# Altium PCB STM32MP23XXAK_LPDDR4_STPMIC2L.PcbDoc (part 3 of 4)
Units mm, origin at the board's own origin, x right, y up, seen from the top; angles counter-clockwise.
Board outline 120 x 79.6 mm, 4 copper layers (Top Layer, Signal Layer 1, Signal Layer 2, Bottom Layer), stack 1.614 mm thick; 156 components, 124 nets, 1131 pads, 692 vias.
Unrouted connection lines stored in the file: 3.
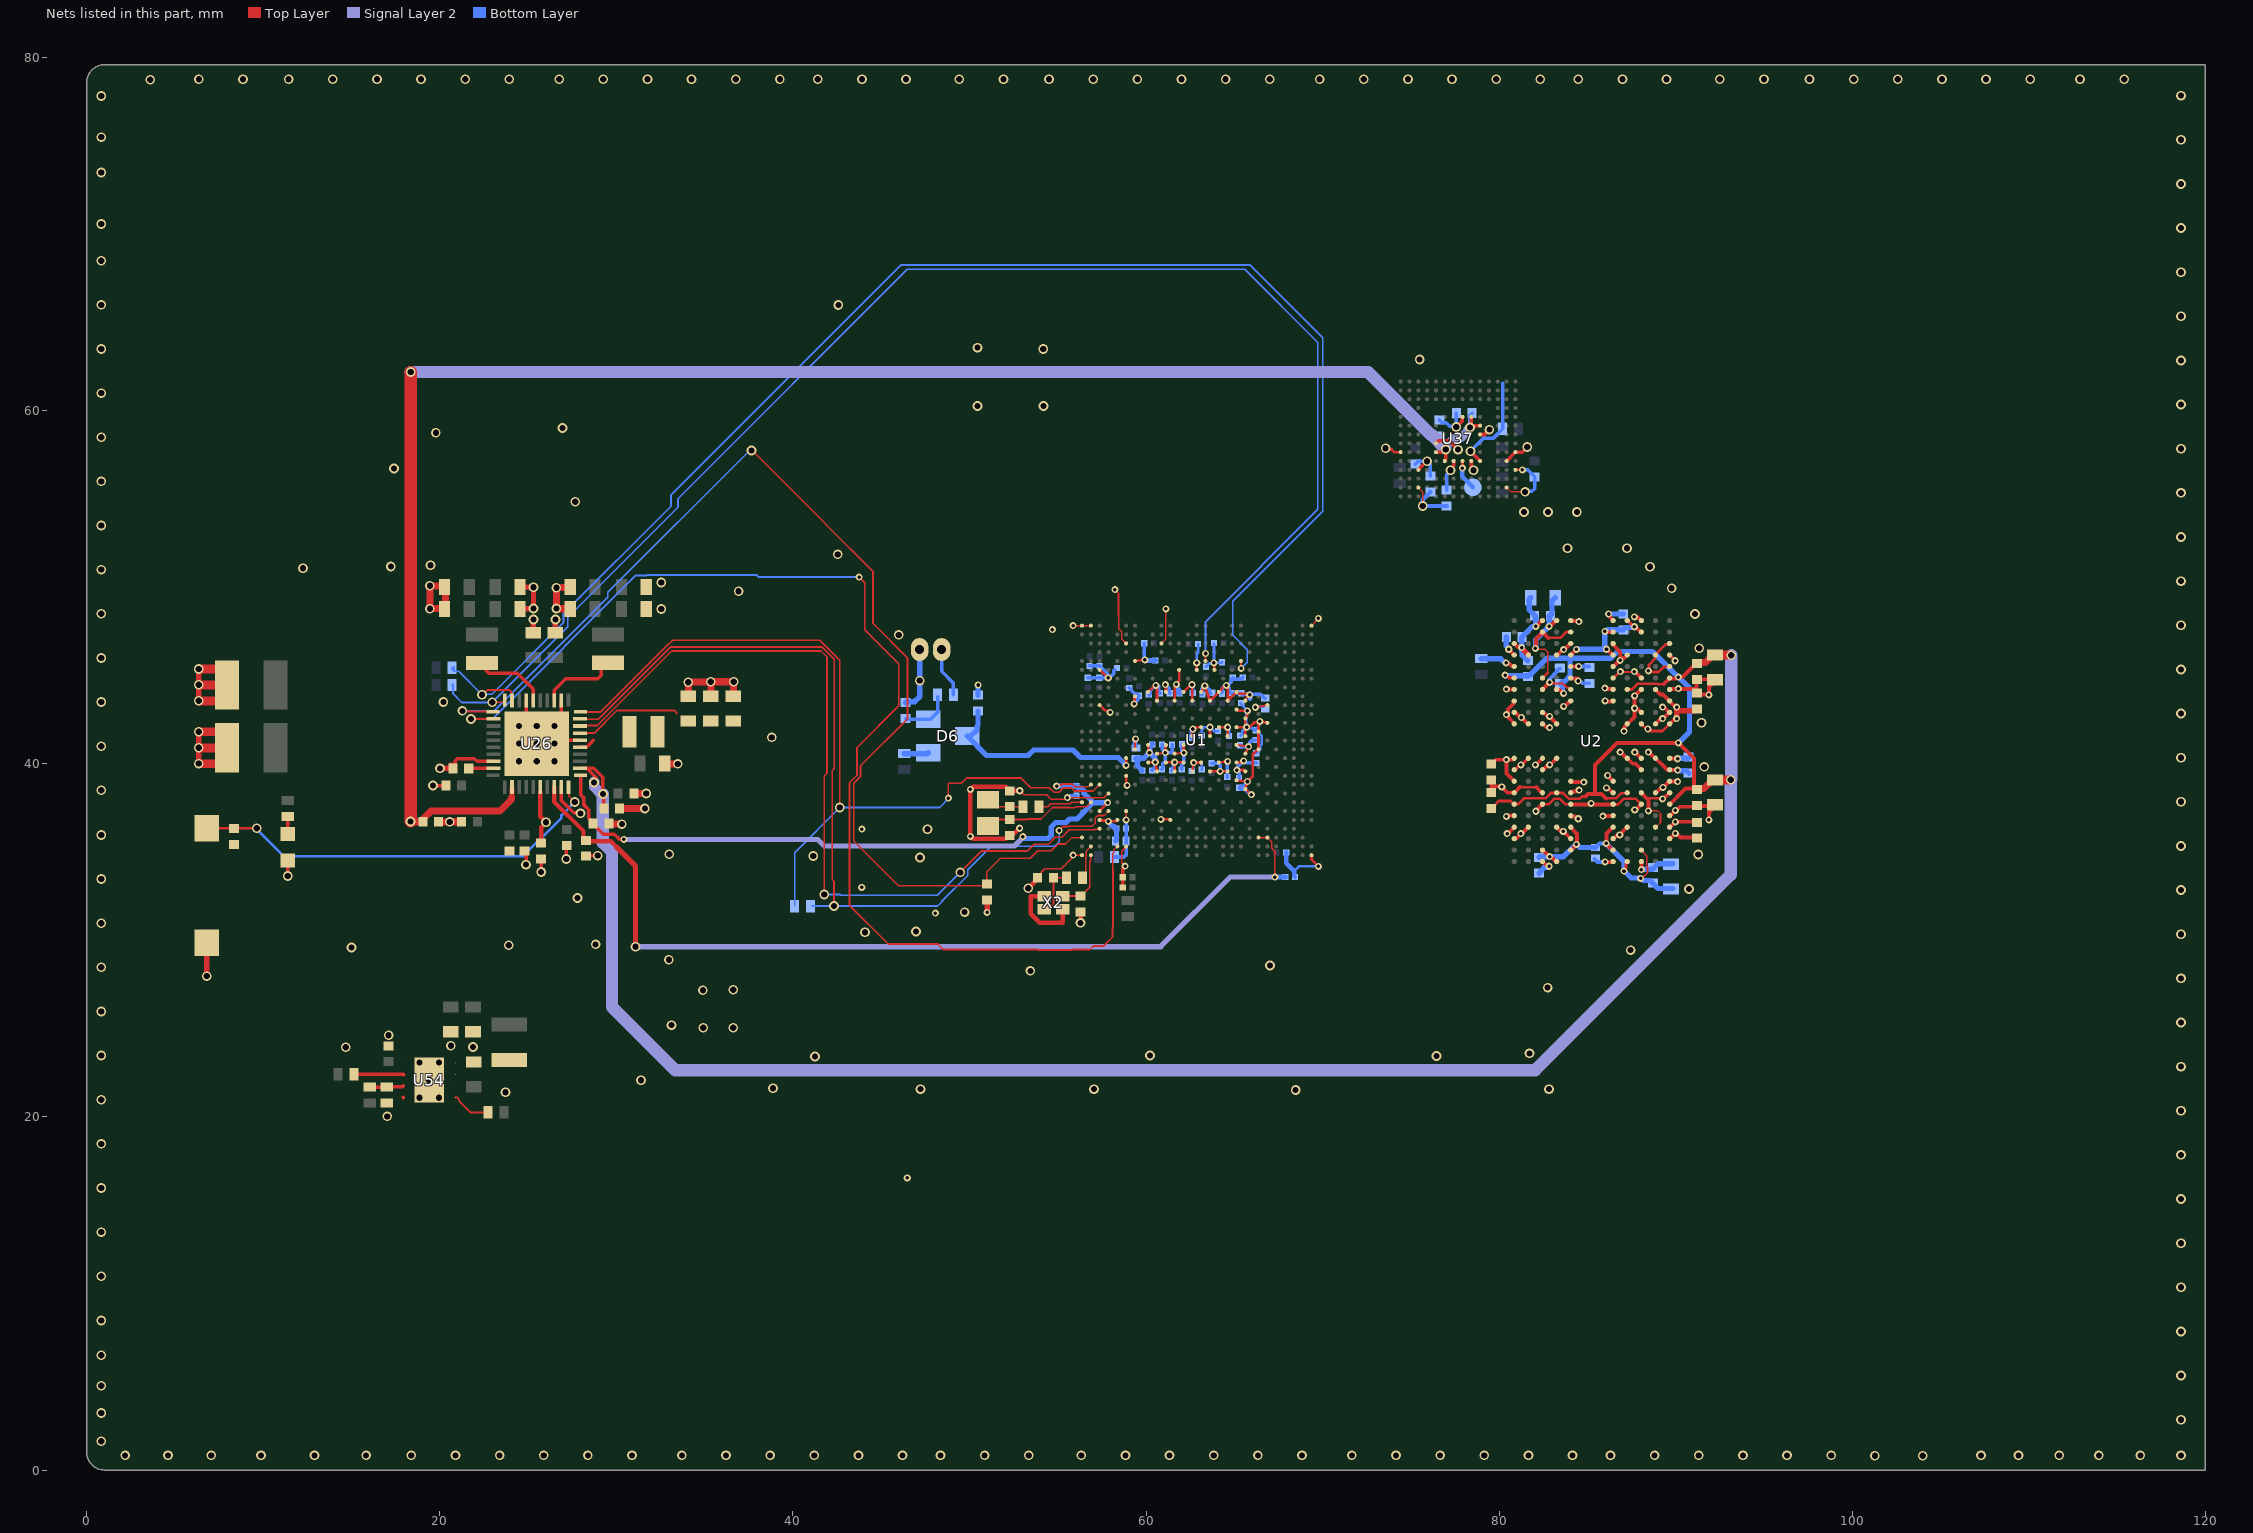
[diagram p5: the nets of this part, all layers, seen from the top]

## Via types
v1: diameter 0.55, hole 0.35, Top Layer to Bottom Layer, 364 vias
v2: diameter 0.4, hole 0.2, Top Layer to Bottom Layer, tented both sides, 223 vias
v3: diameter 0.4, hole 0.2, Top Layer to Bottom Layer, 105 vias

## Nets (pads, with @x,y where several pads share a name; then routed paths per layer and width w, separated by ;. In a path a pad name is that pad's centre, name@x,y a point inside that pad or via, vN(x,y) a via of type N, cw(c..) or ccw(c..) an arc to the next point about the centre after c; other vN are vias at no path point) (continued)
GND: B2.1 C2.1 C3.1 C4.2 C5.2 C6.2 C7.2 C8.2 C9.1 C10.1 C11.1 C12.2 C13.2 C14.2 C15.2 C16.2 C17.2 C18.2 C19.2 C20.2 C21.2 C22.1 C23.1 C24.1 C26.1 C27.1 C28.1 C29.1 C32.1 C33.1 C34.1 C35.1 C36.1 C38.1 C39.1 C40.2 C41.1 C42.2 C44.2 C45.1 C46.1 C47.2 C48.1 C49.1 C50.1 C51.1 C52.1 C53.1 C54.1 C55.1 C56.1 C57.1 C58.1 C59.1 C60.1 C61.2 C62.2 C63.1 C64.1 C65.2 C66.1 C67.1 C68.1 C69.1 C70.2 C71.1 C72.1 C73.2 C74.1 C75.1 C76.1 C77.2 C81.2 C82.1 C83.1 C86.2 C87.1 C88.1 C90.1 C92.2 C117.1 C118.1 C123.1 C128.1 C130.1 C147.2 C148.1 C183.1 C185.2 C189.2 C190.2 C192.1 C193.2 C195.1 C196.1 C197.1 C200.1 C201.1 C202.1 C205.1 C208.1 C209.1 C213.1 C214.1 C215.1 C219.1 C220.1 C225.1 C234.1 C235.1 C236.1 C237.1 C238.1 C239.1 C240.1 C244.1 C246.1 C248.1 C250.1 C251.1 CN12.2 LD11.2 R1.1 R42.1 R57.1 U1.1A1 U1.1A3 U1.1A5 U1.1A7 U1.1A9 U1.1A11 U1.1B2 U1.1B4 U1.1B6 U1.1B8 U1.1B10 U1.1B12 U1.1E7 U1.1E9 U1.1F6 U1.1F8 U1.1F10 U1.1G1 U1.1G3 U1.1G5 U1.1G11 U1.1H2 U1.1H4 U1.1H12 U1.1J1 U1.1J3 U1.1J5 U1.1J7 U1.1J9 U1.1J11 U1.1K2 U1.1K4 U1.1K6 U1.1K8 U1.1K10 U1.1K12 U1.A1 U1.A2 U1.A27 U1.AC3 U1.AC5 U1.AC11 U1.AF6 U1.AG1 U1.AG27 U1.C6 U1.C10 U1.E7 U1.F3 U1.F12 U1.F14 U1.F16 U1.J7 U1.K3 U1.V6 U1.Y4 U2.A3 U2.A10 U2.AB3 U2.AB5 U2.AB8 U2.AB10 U2.C1 U2.C5 U2.C8 U2.C12 U2.D2 U2.D4 U2.D9 U2.D11 U2.E1 U2.E5 U2.E8 U2.E12 U2.G1 U2.G3 U2.G5 U2.G8 U2.G10 U2.G12 U2.J1 U2.J3 U2.J10 U2.J12 U2.K2 U2.K4 U2.K9 U2.K11 U2.N2 U2.N4 U2.N9 U2.N11 U2.P1 U2.P3 U2.P10 U2.P12 U2.T1 U2.T3 U2.T5 U2.T8 U2.T10 U2.T12 U2.V1 U2.V5 U2.V8 U2.V12 U2.W2 U2.W4 U2.W9 U2.W11 U2.Y1 U2.Y5 U2.Y8 U2.Y12 U26.6 U26.12 U26.17 U26.28 U26.39 U26.41 U37.A6 U37.C4 U37.E7 U37.G5 U37.H10 U37.J5 U37.K8 U37.N2 U37.N5 U37.P4 U37.P6 U54.4 U54.8 U54.9 X2.2 X2.4 | length 243
  Top Layer w0.09: v2(55.55,38.085) 55.565,38.07 56.266,38.07 56.271,38.075 57.612,38.075 57.862,38.325 U1.Y4@57.875,38.325 ; U1.A1@56.375,47.825 U1.A2@56.875,47.825 ; 58.445,48.418 58.445,47.647 58.625,47.467 58.625,47.075 U1.C6@58.875,46.825 ; v2(58.816,34.213) 58.625,34.404 58.625,35.05 58.875,35.3 U1.AF6@58.875,35.325 ; U1.C10@60.875,46.825 61.125,47.075 v2(61.125,48.775) ; U37.N2@80.425,55.655 80.675,55.405 v1(81.475,55.405) ; U2.T10@82.459,44.194 U2.T10@82.459,44.207 ; v3@82.859,44.607 82.859,44.619 v3@82.937,44.619 ; v3@86.859,40.669 86.872,40.669 v3@86.884,40.669 ; U2.K4@87.234,40.319 U2.K4@87.259,40.319 ; v3@88.459,37.344 88.467,37.352 88.976,37.352 89.145,37.183 89.145,36.68 U2.D2@88.859,36.394
  Top Layer w0.1: v2(52.85,38.475) 52.882,38.475 53.114,38.244 54.372,38.244 54.622,37.994 55.458,37.994 v2(55.55,38.085) ; v1@53.243,33.041 v1(53.329,32.955) ; C92.2@53.859,33.546 53.859,33.648 54.264,34.053 55.189,34.053 55.279,34.144 55.291,34.144 55.496,34.349 55.496,34.361 55.77,34.635 55.77,34.639 55.875,34.744 v2(55.875,34.825) U1.AG1@56.375,34.825 ; v2(55.875,47.825) U1.A1@56.375,47.825 ; v2(58.24,49.865) 58.445,49.66 58.445,48.418 ; U1.A27@69.375,47.825 69.762,48.213 v2(69.762,48.238) ; v3(83.66,46.465) 83.685,46.465 v3@83.723,46.503 ; U2.Y8@84.035,46.815 U2.Y8@84.06,46.815 ; U2.V8@84.06,45.515 84.064,45.519 U2.V8@84.084,45.519 ; v3@84.505,45.519 v3(84.509,45.523)
  Top Layer w0.125: v3@82.974,44.57 83.12,44.57 83.144,44.545 83.616,44.545 83.835,44.326 83.9,44.326 84.018,44.208 U2.T8@84.018,44.194
  Top Layer w0.15: U1.AC3@57.375,36.825 57.41,36.79 57.795,36.79 57.845,36.74 v2(57.872,36.74) 58.29,36.74 U1.AC5@58.375,36.825 ; U1.K3@57.375,43.325 57.643,43.057 v2(57.966,42.92) ; U1.F3@57.375,45.325 v2(57.862,44.875) ; U1.V6@58.875,39.325 58.875,38.893 58.925,38.843 v2(58.925,38.775) ; v2@59.325,43.275 59.35,43.3 59.35,43.613 ; v2(59.325,43.4) 59.35,43.613 ; U1.E7@59.375,45.825 v2(59.931,45.892) ; U1.J7@59.388,43.812 U1.J7@59.375,43.825 ; U1.1J1@60.125,40.075 v2(60.525,40.1) U1.1K2@60.625,39.575 ; U1.1G1@60.125,41.075 60.125,40.778 60.198,40.705 v2(60.198,40.638) ; U1.1A1@60.125,44.075 60.442,44.392 60.481,44.392 60.531,44.442 v2@60.555,44.442 ; v2(60.558,44.442) v2@60.555,44.442 ; U1.1H2@60.625,40.575 v2(61.092,40.638) U1.1G3@61.125,41.075 ; U1.1B2@60.625,43.575 60.625,44.371 v2@60.555,44.442 ; v2(60.841,36.854) 61.289,36.854 61.303,36.84 61.36,36.84 U1.AC11@61.375,36.825 ; U1.1J3@61.125,40.075 v2(61.625,40.089) ; U1.1A3@61.125,44.075 61.132,44.082 v2@61.132,44.466 ; U1.1K4@61.625,39.575 v2(61.625,40.089) ; U1.1H4@61.625,40.575 v2(62.15,40.625) U1.1G5@62.125,41.075 ; U1.1B4@61.625,43.575 61.625,44.405 v2(61.725,44.505) 61.725,44.573 61.875,44.723 U1.F12@61.875,45.325 ; U1.1J5@62.125,40.075 v2(61.625,40.089) ; U1.1A5@62.125,44.075 62.496,44.446 62.571,44.446 62.625,44.5 U1.1B6@62.625,43.575 ; U1.1K6@62.625,39.575 v2(62.7,40.075) U1.1J7@63.125,40.075 ; U1.1F6@62.625,41.575 62.625,41.95 v2(62.65,41.975) ; v2@62.657,41.975 62.718,41.975 62.818,42.075 U1.1E7@63.125,42.075 ; U1.F14@62.875,45.325 v2(62.875,45.725) ; U1.1A7@63.125,44.075 v2(63.328,44.412) U1.1B8@63.625,43.575 U1.1A9@64.125,44.075 64.448,44.398 64.538,44.398 64.586,44.446 64.625,44.407 U1.1B10@64.625,43.575 U1.1A11@65.125,44.075 65.147,44.075 65.25,43.972 65.818,43.972 65.865,43.925 65.865,43.894 65.64,43.669 65.64,43.59 U1.1B12@65.625,43.575 ; U1.1K8@63.625,39.575 v2(64.198,39.575) U1.1K10@64.625,39.575 ; U1.1F8@63.625,41.575 v2(63.625,42.075) ; v2@63.853,45.725 U1.F16@63.875,45.325 ; U1.1E9@64.125,42.075 v2(64.625,42.075) U1.1F10@64.625,41.575 ; U1.1G11@65.125,41.075 v2(65.806,40.972) U1.1H12@65.625,40.575 ; U1.AG27@69.375,34.825 69.375,34.59 v2(69.768,34.197) ; v1(73.575,57.875) 73.646,57.804 73.911,57.804 74.056,57.66 74.42,57.66 U37.A6@74.425,57.655 ; U37.P4@80.925,56.655 v2(81.325,56.655) ; 81.193,38.681 81.527,38.681 81.531,38.684 81.791,38.684 81.795,38.681 82.106,38.681 ; v3@82.937,44.619 82.937,44.609 82.974,44.572 v3@82.974,44.57 ; U2.T8@84.018,44.194 U2.T8@84.059,44.194 ; 88.348,38.055 88.724,38.055 88.729,38.05 89.228,38.05 v3@89.259,38.019 ; U2.W2@88.859,46.169 88.859,46.196 89.433,46.77 89.562,46.77 U2.Y1@89.608,46.816 ; U2.W2@88.86,46.168 88.843,46.151 88.843,45.957 88.495,45.609 88.495,45.298 88.45,45.253 88.486,45.217 88.711,45.217 88.729,45.2 89.033,45.2 89.334,45.501 U2.V1@89.652,45.501 ; 59.35,43.613 59.35,43.825 U1.J7@59.375,43.825 ; 59.35,43.613 U1.J7@59.375,43.825
  Top Layer w0.16: U1.1J9@64.125,40.075 v2(64.625,40.143) ; U1.1J11@65.125,40.075 65.435,40.075 v2(65.53,40.17) ; v2(65.15,39.65) 65.55,39.65 U1.1K12@65.625,39.575
  Top Layer w0.2: v1@11.386,33.645 LD11.2@11.386,34.522 ; U54.4@17.926,21.107 17.936,21.097 ; v1(19.613,38.769) C209.1@20.288,38.769 ; C208.1@20.582,39.981 C208.1@20.719,39.981 ; C208.1@20.719,39.819 C208.1@20.719,39.981 ; U26.28@23.038,40.144 22.112,40.144 21.957,40.299 20.991,40.299 20.874,40.182 20.874,39.999 20.857,39.981 C208.1@20.719,39.981 ; v1@24.888,34.292 C123.1@24.888,35.119 ; U26.17@24.888,43.594 24.888,41.744 v1(25.488,41.144) U26.41@25.668,41.324 ; v1(25.738,33.869) C215.1@25.738,34.519 ; U26.41@26.386,41.185 26.544,41.344 U26.6@27.938,41.344 ; U26.41@26.386,41.324 U26.41@25.668,41.324 ; U26.39@26.888,38.694 26.888,37.919 27.58,37.226 27.932,37.226 v1(27.963,37.196) ; U26.12@26.888,43.594 26.888,42.544 U26.41@25.668,41.324 ; v1@27.163,34.587 C193.2@27.163,35.389 ; C61.2@28.307,34.8 28.322,34.784 28.934,34.784 v1(28.95,34.8) ; C248.1@58.683,33.002 C250.1@58.683,33.572 58.683,34.08 v2(58.816,34.213) ; U37.C4@75.425,56.655 75.875,57.105 75.885,57.105 v1(75.925,57.145) ; U37.E7@76.425,58.155 76.575,58.305 77.17,58.305 v1(77.675,57.8) ; v1(77.25,56.63) 77.25,56.718 77.425,56.893 U37.G5@77.425,57.155 ; v1(77.575,59.08) 77.925,59.43 U37.H10@77.925,59.655 ; U37.J5@78.425,57.155 78.425,56.85 78.55,56.725 v1(78.55,56.63) ; U37.K8@78.925,58.655 79.175,58.655 v1(79.45,58.93) ; U37.N5@80.425,57.155 U37.P6@80.925,57.655 81.305,57.655 v1(81.6,57.95) ; U2.J12@80.86,39.665 80.914,39.665 81.164,39.915 81.247,39.915 81.648,40.315 U2.K11@81.66,40.315
  Top Layer w0.22: C5.2@79.559,38.379 79.559,38.73 ; C13.2@79.559,39.08 79.559,38.73 ; v3@80.151,38.625 v3@80.2,38.625 ; v3(80.4,45.719) 80.527,45.719 80.693,45.554 80.765,45.554 80.788,45.53 80.85,45.53 U2.V12@80.86,45.521 ; v3@80.41,37.025 80.45,37.065 U2.E12@80.86,37.065 ; v3@80.425,44.215 U2.T12@80.86,44.215 ; U2.G12@80.83,38.38 U2.G12@80.845,38.365 ; U2.G12@80.854,38.356 U2.G12@80.845,38.365 ; U2.P12@80.859,42.894 80.874,42.879 80.949,42.879 81.149,42.679 81.17,42.679 81.293,42.556 81.293,42.535 81.347,42.535 81.637,42.244 U2.N11@81.659,42.244 ; U2.C12@80.86,35.765 80.875,35.78 80.975,35.78 v3(81.24,36.045) 81.288,36.045 U2.D11@81.658,36.415 ; U2.G12@80.86,38.365 U2.G12@80.845,38.365 ; U2.Y12@80.86,46.815 80.882,46.815 81.073,46.623 81.236,46.623 v3(81.271,46.589) ; U2.G12@80.87,38.36 81.19,38.681 81.193,38.681 ; v3(82.085,47.79) 82.113,47.79 82.438,48.115 U2.AB10@82.46,48.115 ; 82.106,38.681 82.378,38.409 82.399,38.409 82.452,38.356 U2.G10@82.456,38.356 ; U2.A10@82.459,34.444 82.465,34.45 82.496,34.45 82.716,34.229 82.799,34.229 v3@82.833,34.195 ; U2.J10@82.459,39.644 82.481,39.644 82.721,39.885 82.825,39.885 82.859,39.919 82.872,39.919 83.247,40.294 U2.K9@83.259,40.294 ; U2.P10@82.459,42.894 82.474,42.879 82.557,42.879 82.842,42.594 v3@82.897,42.594 ; U2.T10@82.459,44.207 v3@82.859,44.607 ; v3(82.86,42.69) 82.859,42.677 83.259,42.278 U2.N9@83.259,42.265 ; U2.W9@83.259,46.144 83.281,46.144 83.571,46.435 83.625,46.435 83.693,46.503 v3@83.723,46.503 ; U2.D9@83.26,36.415 83.5,36.175 v3(83.635,36.175) ; v3@83.641,36.175 U2.C8@84.059,35.756 ; v3@83.747,46.503 v3@83.723,46.503 ; U2.Y8@84.035,46.815 v3@83.723,46.503 ; U2.E8@84.059,37.044 84.074,37.029 84.301,37.029 84.435,36.894 v3@84.484,36.894 ; U2.G8@84.059,38.365 84.081,38.365 84.16,38.444 84.336,38.444 84.372,38.481 84.497,38.481 v3@84.534,38.444 ; U2.AB8@84.06,48.115 84.075,48.1 84.421,48.1 84.466,48.054 v3(84.515,48.054) ; U2.V8@84.072,45.507 U2.V8@84.084,45.519 ; U2.V8@84.088,45.523 U2.V8@84.084,45.519 ; v3@84.505,45.519 U2.V8@84.084,45.519 ; v3@85.885,37.04 85.891,37.046 86.384,37.046 86.388,37.05 86.445,37.05 U2.E5@86.46,37.065 ; v3(85.99,44.285) 86.039,44.285 86.093,44.23 86.445,44.23 U2.T5@86.46,44.215 ; v3(86.085,38.64) 86.118,38.606 86.197,38.606 U2.G5@86.446,38.356 ; v3(86.21,48.489) 86.244,48.455 86.244,48.352 86.46,48.137 U2.AB5@86.46,48.115 ; U2.C5@86.459,35.744 86.461,35.744 86.663,35.946 86.791,35.946 U2.D4@87.26,36.415 ; U2.V5@86.46,45.515 86.482,45.515 86.832,45.865 v3(86.86,45.865) v3@86.86,45.988 ; U2.Y5@86.46,46.815 86.475,46.8 86.475,46.716 86.86,46.331 v3@86.86,45.988 ; v3@86.8,35.946 v3(86.835,35.981) ; v3@86.872,40.669 87.247,40.294 U2.K4@87.259,40.294 ; v3(87.075,41.85) 87.109,41.884 87.109,42.093 U2.N4@87.26,42.243 ; U2.K4@87.259,40.315 87.57,40.004 87.72,40.004 U2.J3@88.059,39.665 ; U2.N4@87.26,42.265 U2.N4@87.26,42.243 ; U2.W4@87.26,46.165 87.083,45.988 v3@86.86,45.988 ; v3(87.661,48.325) 87.695,48.291 87.863,48.291 88.038,48.115 U2.AB3@88.06,48.115 ; v3@87.678,43.153 87.715,43.116 87.838,43.116 88.038,42.915 U2.P3@88.06,42.915 ; v3@88.059,33.994 U2.A3@88.059,34.444 ; U2.G3@88.059,38.344 88.348,38.055 88.459,37.944 v3@88.459,37.344 ; U2.T3@88.06,44.215 88.04,44.215 v3(87.675,43.85) v3(87.675,43.15) 87.675,42.658 U2.N4@87.26,42.243 ; v3@88.459,40.669 88.472,40.669 88.847,40.294 U2.K2@88.859,40.294 ; U2.N2@88.859,42.244 89.15,42.535 89.225,42.535 v3@89.259,42.569 ; U2.K2@88.86,40.315 89.531,39.644 89.659,39.644 v3@90.109,39.644 ; v3@89.259,38.019 89.293,38.053 89.347,38.053 89.637,38.344 U2.G1@89.659,38.344 ; v3@89.259,43.219 89.334,43.219 U2.P1@89.638,42.915 ; v3(89.26,42.565) 89.288,42.565 U2.P1@89.638,42.915 ; U2.C1@89.659,35.744 89.954,36.039 v3@89.954,36.147 ; U2.E1@89.659,37.044 89.672,37.044 89.972,37.344 90.033,37.344 90.258,37.569 C7.2@91.159,37.569 ; U2.P1@89.659,42.894 U2.P1@89.638,42.915 ; U2.T1@89.659,44.194 U2.T1@89.681,44.194 ; U2.T1@89.659,44.244 C14.2@91.184,44.244 ; U2.P1@89.66,42.915 U2.P1@89.638,42.915 ; v3@90.033,36.069 90.033,36.066 90.068,36.031 90.071,36.031 90.283,35.819 C15.2@91.159,35.819 ; C7.2@91.159,37.694 C7.2@91.247,37.607 ; C7.2@91.245,37.606 92.095,37.606 C3.1@92.183,37.519 ; C14.2@91.263,43.939 91.85,43.939 v3(91.884,43.905) 91.899,43.92 91.899,44.36 92.083,44.544 91.833,44.794 91.184,44.794 C14.2@91.184,44.244 ; C14.2@91.264,43.939 91.184,44.019 C14.2@91.184,44.244 ; v3(91.884,36.829) 91.899,36.845 91.899,37.255 92.138,37.494 92.233,37.494 C3.1@92.208,37.519 ; 79.559,38.73 80.121,38.73 v3(80.15,38.7) 80.485,38.365 U2.G12@80.845,38.365
  Top Layer w0.25: v2(52.841,36.352) 52.569,36.08 52.415,36.08 C86.2@52.285,35.95 52.26,35.95 52.061,35.75 50.196,35.75 v2(50.05,35.897) v2(50.05,38.554) 50.196,38.7 52.06,38.7 C81.2@52.285,38.475 v2(52.85,38.475) ; v1(53.329,32.955) 53.729,33.355 53.729,33.416 C92.2@53.859,33.546 ; X2.2@54.234,32.51 53.467,32.51 53.467,31.513 53.987,30.993 55.284,30.993 X2.4@55.284,31.76 ; v1(56.293,30.993) C90.1@56.293,31.61
  Top Layer w0.3: v1@6.347,40.012 v1@6.347,41.812 ; v1@6.347,43.574 v1@6.347,45.374 ; B2.1@6.795,29.854 6.795,27.98 v1(6.8,27.975) ; v1(20.013,39.744) C208.1@20.738,39.744 ; U26.41@24.468,40.124 v1(24.488,40.144) v1(25.488,41.144) ; C23.1@24.509,49.935 24.584,50.009 25.291,50.009 25.308,49.992 25.308,48.808 25.284,48.784 24.607,48.784 C24.1@24.558,48.834 ; v1(25.3,48.175) 25.294,48.169 25.294,47.454 C29.1@25.336,47.412 ; C38.1@26.538,47.414 26.544,47.42 26.544,48.169 v1(26.55,48.175) ; v2@50.979,31.565 v2(51,31.586) C33.1@51,32.3 ; v3(80.41,44.23) v3@80.425,44.215 ; v3(81.271,46.589) 81.271,46.562 81.66,46.173 U2.W11@81.66,46.165
  Top Layer w0.4: v1(19.436,48.785) v1(19.436,50.085) C22.1@20.143,50.085 ; v1@19.535,48.789 C183.1@20.238,48.789 ; C190.2@19.888,36.764 19.938,36.714 v1(20.563,36.714) ; C22.1@20.143,49.835 20.263,49.955 C22.1@20.263,50.019 ; C183.1@20.316,48.994 C22.1@20.316,50.064 ; v1@20.568,36.719 C185.2@21.238,36.719 ; C27.1@27.384,50.009 27.372,49.997 26.622,49.997 v1(26.6,49.975) v1(26.6,48.8) 26.616,48.784 C26.1@27.409,48.784 ; C189.2@29.613,36.589 v1@30.307,36.589 ; C40.2@30.143,37.469 C40.2@30.188,37.469 v1(31.613,37.469) ; C39.1@31,38.325 31.006,38.319 v1(31.688,38.319) ; C32.1@32.7,40 v1(33.475,40) ; C200.1@34.075,43.895 v1(34.075,44.625) 34.087,44.638 35.338,44.638 v1(35.35,44.65) ; C202.1@35.453,43.829 35.35,43.932 v1(35.35,44.65) ; C41.1@36.625,43.825 36.638,43.838 36.638,44.638 v1@36.64,44.64 ; v1(36.65,44.65) v1(35.35,44.65)
  Top Layer w0.5: v1@6.353,40.006 C147.2@7.936,40.006 ; v1@6.353,40.906 C147.2@7.936,40.906 ; v1@6.353,41.818 C147.2@7.936,41.818 ; v1@6.353,43.568 C42.2@7.936,43.568 ; v1@6.353,44.468 C42.2@7.936,44.468 ; v1@6.353,45.38 C42.2@7.936,45.38
  Bottom Layer w0.1: C8.2@83.459,45.39 83.459,45.438 C8.2@83.461,45.44
  Bottom Layer w0.15: v2(59.931,45.892) v2@59.935,45.896 ; C57.1@62.592,39.603 62.683,39.694 62.683,40.058 v2(62.7,40.075) 63.066,40.075 63.154,39.987 C60.1@63.154,39.672 ; v2(62.875,45.725) 62.875,46.219 62.95,46.294 C195.1@62.95,46.787 ; C52.1@63.162,41.607 63.162,41.944 63.293,42.075 v2(63.625,42.075) 63.844,41.856 C53.1@64.083,41.856 ; C67.1@63.4,45.5 63.586,45.686 63.807,45.686 v2@63.859,45.738 ; v2(63.85,45.725) 64.278,45.725 C69.1@64.305,45.752 ; v2@63.85,45.775 C239.1@63.85,46.787 ; v2(64.625,42.075) 64.706,41.994 C54.1@64.706,41.579 ; 68.39,33.919 68.669,34.197 v2(69.768,34.197)
  Bottom Layer w0.2: v2(55.55,38.085) 55.663,38.198 C234.1@56.064,38.198 ; C237.1@56.696,44.88 C236.1@57.345,44.88 ; C192.1@56.8,45.55 C201.1@57.375,45.55 57.825,45.1 57.825,44.912 v2(57.862,44.875) 57.862,44.894 57.881,44.914 57.974,44.914 58.163,45.103 58.163,45.282 C197.1@58.216,45.334 ; C236.1@57.35,44.875 v2(57.862,44.875) ; C240.1@59.05,44.3 59.37,43.98 59.484,43.98 59.534,43.93 C220.1@59.534,43.856 ; v2(59.325,43.4) 59.325,43.408 59.534,43.617 59.534,43.781 C220.1@59.609,43.856 C220.1@59.534,43.931 ; v2@59.902,45.948 C205.1@59.902,46.829 ; C45.1@60.173,43.895 60.235,43.957 60.235,44.124 60.248,44.137 60.248,44.139 60.551,44.442 v2(60.558,44.442) ; C71.1@60.34,39.635 60.491,39.786 60.491,40.066 v2(60.525,40.1) ; v2@60.624,44.485 60.726,44.383 60.726,44.075 C51.1@60.813,43.988 ; C72.1@60.905,39.698 60.956,39.749 60.956,40.021 61.092,40.157 v2(61.092,40.638) ; C46.1@60.915,41.105 60.915,40.815 v2(61.092,40.638) ; v2@61.132,44.466 61.132,44.444 61.302,44.274 61.302,44.062 C49.1@61.377,43.987 ; C73.2@61.467,39.624 61.542,39.699 61.542,39.952 61.625,40.035 v2(61.625,40.089) ; C47.2@61.476,41.081 61.476,40.694 61.42,40.638 v2(61.092,40.638) ; C74.1@62.03,39.683 62.03,39.955 62.15,40.075 v2(62.15,40.625) 62.038,40.737 C48.1@62.038,41.107 ; C63.1@62.581,44.08 62.636,44.08 62.636,44.483 v2@62.625,44.494 ; C62.2@63.156,43.924 63.156,44.24 v2(63.328,44.412) 63.366,44.374 63.421,44.374 63.6,44.195 63.6,44.059 C65.2@63.675,43.984 ; C59.1@63.714,40.036 64.111,40.036 64.198,39.949 v2(64.198,39.575) ; C68.1@64.239,43.997 64.314,44.072 64.314,44.284 64.437,44.408 64.548,44.408 v2@64.586,44.446 ; C58.1@64.607,39.247 64.607,40.125 v2(64.625,40.143) ; C66.1@64.915,44.871 C66.1@64.84,44.796 ; C76.1@65.274,39.198 65.274,39.526 v2(65.15,39.65) 65.169,39.669 65.169,39.809 v2(65.53,40.17) 65.557,40.17 65.677,40.05 C77.2@66.25,40.05 ; C82.1@65.352,41.053 65.433,40.972 v2(65.806,40.972) 65.844,41.01 65.844,41.178 66.016,41.35 C75.1@66.205,41.35 ; C238.1@65.483,44.894 65.385,44.796 C66.1@64.84,44.796 ; R1.1@66.751,43.72 66.701,43.72 66.601,43.82 66.601,43.828 66.484,43.946 65.886,43.946 65.865,43.925 65.851,43.939 65.436,43.939 65.375,44 C64.1@64.85,44 64.804,44 64.8,43.996 64.725,44.071 64.725,44.307 v2@64.586,44.446 ; C118.1@75.26,56.98 75.425,57.145 v1(75.925,57.145) 76.11,56.96 C148.1@76.11,56.305 ; C9.1@76.615,59.48 76.77,59.325 77.008,59.325 77.208,59.126 77.529,59.126 v1(77.575,59.08) C117.1@77.575,59.864 ; C130.1@77.027,55.505 77.027,56.407 v1(77.25,56.63) ; v2(81.325,56.655) 81.615,56.655 C128.1@82.015,56.255 82.015,55.592 81.858,55.435 81.505,55.435 v1(81.475,55.405) ; v2@64.586,44.446 64.623,44.446 64.84,44.663 C66.1@64.84,44.796
  Bottom Layer w0.22: v3@82.825,44.749 82.814,44.76 83.291,45.236 83.291,45.295 83.386,45.39 C8.2@83.459,45.39 ; v3(82.86,44.615) 82.893,44.649 v3@82.893,44.777 ; v3(84.509,45.523) 84.511,45.525 C21.2@85.109,45.525
  Bottom Layer w0.25: 67.941,34.367 68.39,33.919 68.39,33.638 C251.1@68.44,33.588 ; 67.941,34.385 C246.1@67.941,34.986
  Bottom Layer w0.3: C88.1@46.382,43.465 46.439,43.522 46.897,43.522 47.189,43.814 CN12.2@47.189,46.897 ; C87.1@50.485,43.888 v2(50.485,44.466) ; v2(57.872,36.74) 57.891,36.721 57.891,36.682 58.133,36.44 58.216,36.44 C244.1@58.325,36.331 58.325,35.675 C235.1@58.275,35.625 ; C70.2@59.775,39.625 59.506,39.894 59.506,40.25 59.456,40.3 C225.1@59.425,40.3 59.451,40.326 59.886,40.326 v2(60.198,40.638) ; v2@59.902,45.948 59.931,45.919 v2(59.931,45.892) 59.958,45.892 60,45.85 C196.1@60.525,45.85 ; C44.2@60.351,41.105 60.217,40.971 60.217,40.657 v2(60.198,40.638) ; v2(60.525,40.1) 60.506,40.119 60.506,40.33 v2(60.198,40.638) ; v2(61.725,44.505) 61.725,44.478 61.75,44.453 61.75,44.284 61.875,44.159 61.875,44.025 C50.1@61.9,44 ; C55.1@62.6,41.475 62.604,41.479 62.604,41.901 62.65,41.948 v2(62.65,41.975) ; v2@65.889,43.718 v2@65.889,43.969 ; v2@69.769,34.192 69.788,34.173 v2@69.829,34.173 ; v1(75.5,62.9) v1@75.51,62.91 ; R42.1@78.986,45.955 80.087,45.955 80.287,45.754 v3@80.314,45.754 ; v3@81.241,46.521 81.279,46.559 C12.2@81.279,47.149 ; 81.28,46.368 81.299,46.349 81.299,46.152 81.604,45.847 C4.2@81.63,45.847 ; C12.2@81.311,47.18 C12.2@81.279,47.149 ; C10.1@81.786,49.415 81.709,49.338 81.709,48.715 82.025,48.399 C16.2@82.025,48.374 ; C16.2@81.984,48.415 C16.2@82.025,48.374 ; v3(82.085,47.79) 82.084,48.315 C16.2@82.025,48.374 ; v3@82.086,47.784 82.067,47.765 81.871,47.765 81.279,47.174 C12.2@81.279,47.149 ; C19.2@82.26,33.805 82.285,33.805 82.39,33.91 82.39,33.962 82.566,34.138 82.741,34.138 82.798,34.195 v3@82.833,34.195 ; v3@86.211,48.484 86.214,48.487 87.032,48.487 C17.2@87.036,48.49 ; v3@88.059,33.99 88.093,34.024 88.668,34.024 88.734,34.09 88.759,34.09 89.009,34.34 C11.1@89.834,34.34 ; v3@90.06,39.64 90.109,39.64 90.143,39.606 90.618,39.606 C20.2@90.759,39.465
  other v1: 101.286,0.805 104,0.805 2.175,0.83 4.6,0.83 7.05,0.83 9.875,0.83 12.9,0.83 15.825,0.83 18.386,0.83 20.886,0.83 23.386,0.83 25.886,0.83 28.386,0.83 30.886,0.83 33.711,0.83 36.211,0.83 38.711,0.83 41.211,0.83 43.711,0.83 46.211,0.83 48.361,0.83 50.861,0.83 53.361,0.83 56.336,0.83 58.836,0.83 61.336,0.83 63.836,0.83 66.336,0.83 68.836,0.83 71.661,0.83 74.161,0.83 76.661,0.83 79.161,0.83 81.661,0.83 84.161,0.83 86.311,0.83 88.811,0.83 91.311,0.83 93.811,0.83 96.311,0.83 98.811,0.83 107.3,0.83 109.425,0.83 111.725,0.83 113.975,0.83 116.325,0.83 118.625,0.83 0.825,1.625 118.625,2.85 0.825,3.225 0.825,4.775 118.625,5.35 0.825,6.5 118.625,7.85 0.825,8.475 118.625,10.35 0.825,10.975 118.625,12.85 0.825,13.475 118.625,15.35 0.825,15.975 118.625,17.85 0.825,18.475 17.026,20.032 118.625,20.35 0.825,20.975 18.851,21.082 19.951,21.082 23.725,21.4 68.475,21.525 47.225,21.575 57.05,21.575 82.825,21.575 38.875,21.625 19.401,22.082 31.4,22.075 118.625,22.85 18.851,23.082 19.951,23.082 41.25,23.425 76.45,23.45 0.825,23.475 60.225,23.475 81.725,23.6 14.675,23.95 21.876,23.957 20.626,24.032 17.101,24.632 33.125,25.2 118.625,25.35 0.825,25.975 82.75,27.325 118.625,27.85 53.45,28.275 0.825,28.475 67.025,28.575 32.975,28.9 87.45,29.45 15,29.6 23.9,29.725 28.825,29.775 118.625,30.35 44.087,30.462 46.975,30.5 0.825,30.975 49.725,31.6 27.8,32.4 118.625,32.85 90.755,32.906 0.825,33.475 11.387,33.648 24.886,34.29 27.161,34.61 47.2,34.7 41.15,34.775 33,34.875 91.285,34.865 118.625,35.35 0.825,35.975 47.625,36.3 30.311,36.585 118.625,37.85 0.825,38.5 91.617,39.829 6.348,40.014 25.488,40.144 26.488,40.144 118.625,40.35 6.348,40.914 0.825,41 24.488,41.144 26.488,41.144 38.8,41.5 6.348,41.814 24.488,42.144 25.488,42.144 26.488,42.144 91.467,42.332 118.625,42.85 0.825,43.5 20.2,43.5 6.348,43.576 6.348,44.476 47.189,44.713 118.625,45.35 6.348,45.376 0.825,46 91.339,46.544 45.995,47.305 118.625,47.85 0.825,48.5 91.101,48.492 32.538,48.769 25.3,48.8 36.925,49.775 89.772,49.948 25.3,50 32.538,50.269 118.625,50.35 0.825,51 12.25,51.075 88.551,51.167 17.225,51.175 19.475,51.25 42.535,51.865 83.87,52.208 87.25,52.216 118.625,52.85 0.825,53.5 81.406,54.265 82.774,54.265 84.406,54.265 27.675,54.85 118.625,55.35 0.825,56 17.4,56.725 118.625,57.85 0.825,58.5 19.775,58.75 26.95,59.025 50.45,60.275 54.195,60.275 118.625,60.35 0.825,61 118.625,62.85 0.825,63.5 54.175,63.5 50.45,63.575 118.625,65.35 0.825,66 42.575,65.995 118.625,67.85 0.825,68.5 118.625,70.35 0.825,70.575 118.625,72.85 0.825,73.5 118.625,75.35 0.825,75.5 0.825,77.825 118.625,77.85 3.6,78.75 6.35,78.775 8.85,78.775 11.436,78.775 13.936,78.775 16.436,78.775 18.936,78.775 21.436,78.775 23.936,78.775 26.761,78.775 29.261,78.775 31.761,78.775 34.261,78.775 36.761,78.775 39.261,78.775 41.411,78.775 43.911,78.775 46.411,78.775 49.425,78.775 51.925,78.775 54.511,78.775 57.011,78.775 59.511,78.775 62.011,78.775 64.511,78.775 67.011,78.775 69.836,78.775 72.336,78.775 74.836,78.775 77.336,78.775 79.836,78.775 82.336,78.775 84.486,78.775 86.986,78.775 89.486,78.775 92.5,78.775 95,78.775 97.586,78.775 100.086,78.775 102.586,78.775 105.086,78.775 107.586,78.775 110.086,78.775 112.911,78.775 115.411,78.775
  other v2: 46.475,16.55 48.075,31.55 43.9,33 43.902,36.305 65.87,43.91 64.55,44.448 61.1,44.49 62.606,44.48 54.694,47.6
  other v3: 88.06,34.015 82.83,34.2 89.985,36.065 84.485,36.89 80.41,37.02 85.885,37.04 88.46,37.34 89.985,37.365 89.26,38.015 84.535,38.515 90.11,39.64 82.86,39.94 81.235,39.945 86.86,40.665 88.46,40.665 81.26,42.625 89.26,43.215 90.16,44.265 88.46,45.265
HSE_IN: C90.2 U1.AG2 X2.1 | length 3.6
  Top Layer w0.1: X2.1@55.284,32.51 56.318,32.51 56.814,33.005 56.814,34.464 56.875,34.525 U1.AG2@56.875,34.825
HSE_OUT: R75.2 U1.AF2 | length 2
  Top Layer w0.09: 56.59,34.075 56.59,34.686 56.625,34.721 56.625,35.075 U1.AF2@56.875,35.325
  Top Layer w0.1: R75.2@56.409,33.546 56.59,33.727 56.59,34.075
I2C7.SCL: R261.1 U1.E15 U26.20 | length 83.8
  Top Layer w0.1: v1(22.97,43.494) 23.638,43.494 23.688,43.544 U26.20@23.688,43.619 ; U1.E15@63.375,45.825 v2(63.375,46.25)
  Bottom Layer w0.1: R261.1@20.693,44.469 20.701,44.469 R261.1@20.696,44.464 ; R261.1@20.725,44.5 R261.1@20.728,44.497 ; R261.1@20.738,44.506 R261.1@20.728,44.497 ; v1@22.817,43.45 v1@22.925,43.45 ; v2(63.375,46.25) 63.375,48.054 69.733,54.412 69.733,63.865 65.588,68.01 46.487,68.01 33.493,55.016 33.493,54.543 27.243,48.293 27.243,47.767 v1(22.97,43.494) 22.945,43.469 21.256,43.469 20.75,43.975 20.75,44.475 R261.1@20.728,44.497
I2C7.SDA: R260.1 U1.E19 U26.19 | length 86.7
  Top Layer w0.1: v1@22.436,43.919 22.696,44.179 23.954,44.179 24.058,44.076 24.058,43.642 U26.19@24.1,43.6
  Top Layer w0.125: U1.E19@65.375,45.825 65.375,45.44 v2@65.39,45.425
  Bottom Layer w0.1: R260.1@20.696,45.439 20.696,45.349 R260.1@20.8,45.245 ; R260.1@20.725,45.45 R260.1@20.75,45.475 ; R260.1@20.8,45.5 R260.1@20.8,45.245 ; v1@22.378,43.928 21.062,45.245 R260.1@20.8,45.245 ; v1@22.394,43.944 22.955,43.944 27,47.989 27,48.504 33.099,54.603 33.099,55.234 46.115,68.25 65.899,68.25 70.009,64.14 70.009,54.304 64.91,49.206 64.91,47.299 65.74,46.469 65.74,45.76 v2(65.39,45.41)
  other v1: 22.388,43.919
NetB2_2: B2.2 C219.2 U26.40 | length 23.8
  Top Layer w0.1: U26.40@27.288,38.669 27.304,38.652 27.304,38.177 v1(27.638,37.844)
  Top Layer w0.15: B2.2@6.795,36.354 9.621,36.354 v1(9.625,36.35)
  Bottom Layer w0.15: v1@9.625,36.3 11.156,34.769 24.724,34.769 26.88,36.925 26.88,37.086 v1(27.638,37.844)
NetC81_1: C81.1 R64.2 X1.1 | length 2.1
  Top Layer w0.1: X1.1@51.059,37.975 51.459,37.575 C81.1@52.285,37.575 R64.2@53.035,37.575
NetC88_2: C88.2 D6.2 R66.2 | length 2.9
  Bottom Layer w0.2: C88.2@46.382,42.565 46.424,42.523 D6.2@47.673,42.523 47.792,42.523 48.192,42.923 R66.2@48.192,43.796
NetC92_1: C92.1 R75.1 X2.3 | length 2.9
  Top Layer w0.1: X2.3@54.234,31.76 54.461,31.987 54.694,31.987 54.759,32.052 C92.1@54.759,33.546 R75.1@55.509,33.546
NetC130_2: C130.2 C148.2 U37.C2 | length 3.5
  Top Layer w0.09: U37.C2@75.425,55.655 75.675,55.405 v1(75.675,54.605)
  Bottom Layer w0.25: C148.2@76.11,55.405 75.675,54.97 v1(75.675,54.605) C130.2@77.027,54.605
NetC208_2: C208.2 U26.29 | length 1.4
  Top Layer w0.2: C208.2@21.663,39.744 U26.29@23.038,39.744
NetC225_2: C225.2 U1.R7 | length 1.1
  Top Layer w0.1: U1.R7@59.375,40.825 v2@59.375,41.41
  Bottom Layer w0.1: C225.2@59.375,40.95 C225.2@59.425,40.9
  Bottom Layer w0.3: C225.2@59.375,40.95 v2@59.375,41.41
  other v2: 59.41,41.41
NetC235_2: C235.2 C244.2 R267.1 U1.AB6 | length 3.2
  Top Layer w0.09: v2(58.875,36.825) U1.AB6@58.875,37.325
  Bottom Layer w0.2: R267.1@58.223,34.723 58.734,34.723 58.875,34.864 C235.2@58.875,35.625 C244.2@58.875,36.331 v2(58.875,36.825)
NetCN12_1: CN12.1 R66.1 | length 3.2
  Bottom Layer w0.2: CN12.1@48.425,46.801 48.425,45.241 49.083,44.583 R66.1@49.083,43.917
NetD6_1: D6.1 R67.1 | length 1.4
  Bottom Layer w0.3: R67.1@46.3,40.575 47.625,40.575 D6.1@47.673,40.623
NetL2_1: L2.1 U26.16 | length 4.3
  Top Layer w0.2: L2.1@22.388,45.719 22.597,45.51 22.597,45.319 22.777,45.139 24.388,45.139 25.288,44.239 U26.16@25.288,43.594 ; U26.16@25.278,43.524 U26.16@25.278,43.594
NetL3_1: L3.1 U26.13 | length 4.5
  Top Layer w0.2: U26.13@26.488,43.594 26.488,44.173 27.129,44.814 28.939,44.814 29.139,45.014 29.139,45.419 29.439,45.719 L3.1@29.538,45.719
NetL4_1: L4.1 U54.7
NetL5_1: L5.1 U26.5 | length 0.9
  Top Layer w0.2: U26.5@27.938,40.944 28.321,40.944 28.538,41.161 28.538,41.169 28.696,41.327
NetLD11_1: LD11.1 R210.2 | length 1
  Top Layer w0.2: LD11.1@11.386,36.022 R210.2@11.386,37.015
NetR1_2: R1.2 U1.K22 | length 1.6
  Top Layer w0.15: v2@66.201,43.202 U1.K22@66.875,43.325
  Bottom Layer w0.1: v2@66.201,43.2 66.671,43.2 R1.2@66.6,43.2
  Bottom Layer w0.15: v2@66.201,43.202 66.246,43.247 R1.2@66.6,43.247
  other v2: 66.2,43.205
NetR2_1: R2.1 U2.A5 | length 1.1
  Top Layer w0.22: v3@86.009,34.444 U2.A5@86.459,34.444
  Bottom Layer w0.22: R2.1@85.409,34.615 85.584,34.44 v3@86.009,34.44
  other v3: 86.01,34.45
NetR52_1: R52.1 U54.5 | length 2.3
  Top Layer w0.1: U54.5@20.876,21.107 20.976,21.107 21.101,20.982 21.101,20.882 21.726,20.257 R52.1@22.726,20.257
NetR56_1: R56.1 R57.2 U54.3 | length 1.9
  Top Layer w0.2: R56.1@16.026,21.682 R57.2@17.001,21.682 17.038,21.719 17.888,21.719 U54.3@17.926,21.757
NetR69_2: R69.2 U54.2 | length 2.8
  Top Layer w0.2: R69.2@15.143,22.416 17.934,22.416 17.95,22.4
NetR248_1: R248.1 U37.K5 | length 5.7
  Top Layer w0.2: v1(78.375,57.705) U37.K5@78.925,57.155
  Bottom Layer w0.2: v1(78.375,57.705) 79.125,58.455 79.682,58.455 R248.1@80.207,58.98 80.207,61.55 80.195,61.563
NetTP21_1: TP21.1 U37.H5 | length 1.7
  Top Layer w0.15: v2(77.925,56.755) U37.H5@77.925,57.155
  Bottom Layer w0.25: v2(77.925,56.755) 77.925,56.256 TP21.1@78.516,55.665
NRST: C33.2 U1.AE1 U26.21 | length 67.1
  Top Layer w0.09: 55.444,35.457 55.812,35.825 U1.AE1@56.375,35.825
  Top Layer w0.1: v1(21.275,43) 21.303,42.972 23.055,42.972 U26.21@23.067,42.96 ; v1(37.65,57.75) 37.69,57.75 41.873,53.567 41.873,53.551 44.541,50.883 44.541,47.949 46.497,45.992 46.497,42.556 43.821,39.879 43.821,39.269 43.443,38.89 43.443,35.633 45.978,33.097 50.897,33.097 C33.2@51,33.2 50.975,33.225 50.975,33.875 51.758,34.658 53.449,34.658 53.863,35.073 54.632,35.073 55.016,35.457 55.444,35.457
  Bottom Layer w0.1: v1@21.225,43 v1(21.275,43) 23.077,43 29.517,49.441 29.517,49.717 37.55,57.75 v1(37.65,57.75)
NRSTC1MS: R272.1 U1.W3 U26.10 | length 48.5
  Top Layer w0.09: 56.11,38.46 57.01,38.46 U1.W3@57.375,38.825
  Top Layer w0.1: U26.10@27.868,42.944 29.113,42.944 32.969,46.8 32.983,46.8 33.183,47 41.525,47 42.65,45.875 v1(42.65,37.525) ; v2(48.805,38.061) 48.805,38.872 48.805,38.904 49.542,38.904 49.831,39.194 49.936,39.194 49.938,39.192 50.559,39.192 50.561,39.194 52.93,39.194 53.474,38.65 54.531,38.65 54.787,38.394 55.077,38.394 55.319,38.635 55.764,38.635 55.939,38.46 56.11,38.46
  Bottom Layer w0.1: R272.1@40.1,31.95 40.1,34.975 v1(42.65,37.525) 43.55,37.525 ; 43.556,37.526 48.314,37.526 48.805,38.016 v2(48.805,38.061)
OSC32_IN: C86.1 U1.AA2 X1.2 | length 6.4
  Top Layer w0.09: 55.625,37.525 56,37.525 56.05,37.575 56.625,37.575 U1.AA2@56.875,37.825
  Top Layer w0.1: X1.2@51.059,36.475 51.434,36.85 53.271,36.85 53.296,36.875 54.052,36.875 54.702,37.525 55.625,37.525
OSC32_OUT: R64.1 U1.AA1 | length 2.5
  Top Layer w0.09: 56.05,37.825 U1.AA1@56.375,37.825
  Top Layer w0.1: R64.1@53.935,37.575 54.436,37.575 54.597,37.735 55.695,37.735 55.784,37.825 56.05,37.825
PA0_WKUP: U1.AF5 U26.22 | length 68.8
  Top Layer w0.09: 58.125,34.075 58.125,34.929 58.165,34.969 58.165,35.115 U1.AF5@58.375,35.325
  Top Layer w0.1: v1(21.761,42.535) U26.22@23.092,42.535 ; v2(43.751,50.58) 44.063,50.269 44.063,47.604 45.995,45.672 45.995,43.285 43.631,40.921 43.631,39.348 43.2,38.916 43.2,31.993 45.395,29.797 48.212,29.797 48.525,29.485 53.864,29.485 53.889,29.46 55.786,29.46 55.811,29.485 56.828,29.485 57.032,29.69 57.602,29.69 58.106,30.195 58.106,30.747 58.125,30.765 58.125,34.075
  Bottom Layer w0.1: v1@21.79,42.535 22.959,42.535 31.099,50.675 31.7,50.675 ; 31.743,50.694 37.959,50.694 38.073,50.58 v2(43.751,50.58)
PWR_CPU_ON: R272.2 U1.AB4 U26.9 | length 50.3
  Top Layer w0.09: 55.627,36.457 56.927,36.457 57.125,36.655 57.125,36.929 57.271,37.075 57.625,37.075 U1.AB4@57.875,37.325
  Top Layer w0.095: 55.57,36.455 55.625,36.455
  Top Layer w0.1: U26.9@27.868,42.524 28.976,42.524 33.077,46.625 41.631,46.625 42.341,45.916 42.341,39.741 42.225,39.625 42.225,33.45 42.325,33.35 v1(42.325,31.95) ; v2(55.077,36.225) 55.307,36.455 55.57,36.455
  Bottom Layer w0.1: R272.2@41.075,31.95 v1(42.325,31.95) 48.2,31.95 48.475,32.225 ; 48.438,32.217 49.9,33.679 49.9,34.006 51.228,35.335 54.815,35.335 55.083,35.603 v2@55.083,36.219
PWR_ON: U1.AD3 U26.8 | length 46.6
  Top Layer w0.09: 56.084,36.26 57.09,36.26 57.128,36.298 57.348,36.298 U1.AD3@57.375,36.325
  Top Layer w0.1: U26.8@27.918,42.174 28.912,42.174 33.133,46.395 41.593,46.395 41.931,46.056 41.931,39.467 41.775,39.311 v1(41.775,32.6) ; v1(49.475,33.855) 50.678,35.058 53.276,35.058 53.671,35.453 54.474,35.453 54.865,35.844 55.241,35.844 55.659,36.262 56.082,36.262
  Bottom Layer w0.1: v1(41.775,32.6) 42.675,32.6 42.7,32.575 ; 42.675,32.561 48.18,32.561 v1(49.475,33.855)
VBAT: C87.2 D6.3 U1.T6 | length 12.2
  Top Layer w0.15: v2@58.875,39.933 U1.T6@58.875,40.325
  Bottom Layer w0.3: C87.2@50.485,42.988 50.485,42.185 50.423,42.123 50.423,41.923 50.073,41.573 D6.3@49.873,41.573 50.976,40.471 53.326,40.471 53.642,40.788 55.87,40.788 56.299,40.358 58.427,40.358 v2@58.864,39.921 ; v2@58.831,39.889 v2@58.864,39.921 ; v2(58.875,39.91) v2@58.864,39.921 ; v2@58.875,39.933 v2@58.864,39.921
VDD1_DDR: C2.2 C3.2 C4.1 C5.1 C6.1 C7.1 C8.1 C40.1 U2.F1 U2.F12 U2.G4 U2.G9 U2.T4 U2.T9 U2.U1 U2.U12 U26.2 | length 147
  Top Layer w0.15: C5.1@79.559,37.48 79.584,37.48 C5.1@79.764,37.66 ; C5.1@79.765,37.66 79.765,37.68 79.979,37.894 80.659,37.894 80.859,37.694 80.888,37.723 81.088,37.723 81.415,38.05 82.641,38.05 82.936,38.345 83.277,38.345 83.28,38.348 83.628,38.348 83.945,38.032 84.577,38.032 84.698,38.153 84.893,38.153 ; 86.059,38.044 86.632,38.044 86.925,38.337 87.252,38.337 U2.G4@87.259,38.344 ; U2.T4@87.259,44.215 87.518,44.215 87.837,44.534 88.977,44.534 88.992,44.519 89.33,44.519
  Top Layer w0.2: U26.2@27.938,39.744 U26.2@28.327,39.744 ; 28.861,39.21 U26.2@28.327,39.744 ; C40.1@29.288,37.494 29.288,38.244 v1(29.238,38.294) 29.238,39.234 28.728,39.744 U26.2@28.327,39.744 ; v3(80.34,45.025) 80.421,45.025 80.56,44.886 80.839,44.886 U2.U12@80.86,44.865
  Top Layer w0.22: U2.T9@83.26,44.215 83.275,44.2 83.415,44.2 83.625,43.99 v3(83.659,43.99) ; 84.893,38.153 85.034,38.294 85.44,38.294 ; 86.059,38.044 85.809,38.294 85.44,38.294 ; 89.33,44.519 89.655,44.844 89.659,44.844 v3@90,44.844 ; U2.F1@89.65,37.683 90.561,38.594 91.179,38.594 91.034,38.739 91.034,40.316 v3(90.16,41.19) ; v3@90.075,44.919 90.384,44.919 C6.1@91.159,45.694 ; v3@90.146,41.176 86.685,41.176 85.44,39.931 85.44,38.294
  Top Layer w0.4: C7.1@91.2,38.55 91.245,38.595 91.609,38.595 92.1,39.085 C3.2@92.225,39.085 ; C6.1@91.225,45.7 91.27,45.745 91.684,45.745 92.1,46.16 C2.2@92.225,46.16
  Top Layer w0.5: C3.2@92.225,39.085 v1@93.1,39.085 ; C2.2@92.225,46.16 v1@93.15,46.16
  Signal Layer 2 w0.6: v1@28.75,38.975 28.75,38.704 v1@29.16,38.294
  Signal Layer 2 w0.7: v1@29.16,38.294 v1(29.238,38.294) 29.238,35.537 29.75,35.025 29.75,26.225 33.325,22.65 82.05,22.65 93.125,33.725 v1(93.125,39.1) 93.15,39.125 v1(93.15,46.15)
  Bottom Layer w0.2: v3@80.341,45.019 v3@80.377,44.983 ; C4.1@81.593,44.983 C4.1@81.63,44.947
  Bottom Layer w0.3: v3@80.377,44.983 C4.1@81.593,44.983 ; C4.1@81.63,44.947 81.734,45.052 81.788,45.052 82.721,45.985 84.006,45.985 84.018,45.985 ; C8.1@83.473,44.528 C8.1@83.485,44.54 ; v3(83.659,43.99) 83.59,44.059 83.59,44.435 C8.1@83.485,44.54 ; v3(90.16,41.19) 90.784,41.815 90.784,44.29 v3(90.16,44.915) ; v3@90.159,44.89 88.684,46.365 86.723,46.365 86.343,45.985 84.018,45.985 ; C8.1@83.485,44.54 83.59,44.645 83.694,44.645 84.018,44.969 84.018,45.985
  other v1: 28.738,38.939
VDD2_DDR: C10.2 C11.2 C12.1 C13.1 C14.1 C15.1 C16.1 C17.1 C18.1 C19.1 C20.1 C21.1 C41.2 C75.2 C76.2 C77.1 C82.2 C83.2 C200.2 C202.2 L5.2 R2.2 U1.1C11 U1.1D12 U1.1E11 U1.1F12 U1.1L11 U1.1M12 U1.M22 U1.N21 U1.R21 U2.A4 U2.A9 U2.AA3 U2.AA5 U2.AA8 U2.AA10 U2.AB4 U2.AB9 U2.B3 U2.B5 U2.B8 U2.B10 U2.D1 U2.D5 U2.D8 U2.D12 U2.F3 U2.F5 U2.F8 U2.F10 U2.G2 U2.H1 U2.H5 U2.H8 U2.H12 U2.K1 U2.K3 U2.K10 U2.K12 U2.N1 U2.N3 U2.N10 U2.N12 U2.R1 U2.R5 U2.R8 U2.R12 U2.T2 U2.U3 U2.U5 U2.U8 U2.U10 U2.W1 U2.W5 U2.W8 U2.W12 U26.7 | length 84.7
  Top Layer w0.09: v3@82.121,46.482 82.614,46.482 82.754,46.341 82.754,45.159 ; U2.U5@86.46,44.865 U2.U5@86.48,44.865 ; v3@86.844,45.229 v3(86.865,45.229) 86.89,45.204 87.64,45.204 v3(87.665,45.229) ; U2.AB4@87.26,48.115 U2.AB4@87.285,48.115 ; v3@87.635,47.765 v3(87.659,47.765) ; v3(88.016,33.516) 88.083,33.516 88.405,33.838 88.405,34.168 88.369,34.204 88.369,34.784 U2.B3@88.059,35.094 ; U2.K1@89.659,40.369 U2.K1@89.684,40.369
  Top Layer w0.1: U26.7@27.938,41.744 28.75,41.744 30.026,43.02 33.305,43.02 33.4,42.925 33.4,42.85 ; U2.W8@84.06,46.165 U2.W8@84.06,46.167 ; v3@84.38,46.487 v3(84.38,46.49) ; U2.W1@89.66,46.158 U2.W1@89.66,46.165 ; v3(89.972,45.84) v3@89.972,45.846
  Top Layer w0.15: U1.1L11@65.125,39.075 v2(65.75,39) U1.1M12@65.625,38.575 65.625,38.565 65.9,38.29 65.94,38.29 v2(65.97,38.26) ; U1.1E11@65.125,42.075 65.625,42.075 cw(c65.663,41.93) v2(65.7,42.075) ; U1.1C11@65.125,43.075 65.147,43.075 65.222,43 65.735,43 65.731,42.996 65.731,42.703 65.625,42.597 U1.1D12@65.625,42.575 65.625,42.15 v2(65.7,42.075) ; U1.1F12@65.625,41.575 65.625,42 v2(65.7,42.075) ; v2@65.736,42.111 65.89,42.111 66.137,42.357 v2@66.407,42.357 ; U2.F10@82.459,37.694 82.469,37.704 82.803,37.704 83.129,38.03 83.389,38.03 ; U2.U10@82.46,44.865 82.754,45.159 ; 82.785,47.138 83.478,47.138 83.805,47.465 U2.AA8@84.06,47.465 ; 83.39,38.029 83.43,38.029 83.741,37.719 U2.F8@84.059,37.719 ; U2.F5@86.459,37.694 86.734,37.694 87.072,38.032 87.721,38.032 U2.F3@88.034,37.719 ; U2.U5@86.48,44.865 v3@86.844,45.229
  Top Layer w0.16: v2(65.75,39) 66.042,39.292 66.042,40.512 U1.R21@66.32,40.79 ; U1.R21@66.321,40.79 U1.R21@66.363,40.832 ; U1.R21@66.375,40.825 66.363,40.837 66.363,41.813 U1.N21@66.375,41.825 66.375,42.325 v2(66.45,42.4) 66.493,42.357 66.843,42.357 U1.M22@66.875,42.325 ; v3(87.076,33.92) 87.076,33.985 87.193,34.102 87.193,34.105 87.196,34.108 87.196,34.363 87.26,34.427 U2.A4@87.26,34.465 ; U2.N3@88.06,42.265 88.35,41.975 v3(88.425,41.975) 88.546,41.854 89.249,41.854 U2.N1@89.66,42.265
  Top Layer w0.2: v3@80.546,46.484 v3(80.546,46.49) ; U2.W12@80.86,46.165 U2.W12@80.86,46.171 ; v3(82.835,47.79) 82.873,47.828 v3@82.946,47.828 ; U2.AB9@83.233,48.115 U2.AB9@83.26,48.115 ; v3(85.99,47.505) 86.03,47.465 U2.AA5@86.46,47.465 ; U2.AB4@87.285,48.115 v3@87.635,47.765 ; v3(87.659,47.765) 87.697,47.727 87.771,47.727 88.033,47.465 U2.AA3@88.06,47.465 ; U2.W1@89.66,46.158 v3@89.972,45.846
  Top Layer w0.22: C13.1@79.559,39.979 79.814,40.235 v3(80.415,40.235) ; v3@80.488,36.045 80.51,36.045 U2.D12@80.859,36.394 ; v3@80.546,46.484 U2.W12@80.86,46.171 ; U2.H12@80.859,39.021 80.421,39.459 80.421,40.229 v3(80.415,40.235) ; U2.K12@80.859,40.294 80.856,40.297 U2.K12@80.842,40.297 ; U2.K12@80.86,40.315 U2.K12@80.842,40.297 ; U2.N12@80.86,42.265 80.86,42.301 80.414,42.747 v3(80.414,42.784) 80.414,42.832 80.504,42.922 80.504,42.924 80.51,42.93 80.51,43.093 80.82,43.403 80.82,43.503 80.86,43.543 U2.R12@80.86,43.565 ; v3@82.059,39.919 82.072,39.919 82.447,40.294 U2.K10@82.459,40.294 ; v3@82.086,37.344 82.436,37.694 U2.F10@82.459,37.694 ; v3@82.089,46.574 82.089,47.074 82.459,47.444 82.479,47.444 82.785,47.138 ; U2.B10@82.459,35.094 82.462,35.097 82.493,35.097 82.845,34.744 v3(82.86,34.744) ; U2.N10@82.459,42.244 82.491,42.244 82.497,42.25 82.672,42.074 82.826,42.074 v3@82.86,42.04 ; v3@82.859,34.719 82.893,34.685 82.997,34.685 83.237,34.444 U2.A9@83.259,34.444 ; v3@82.946,47.828 U2.AB9@83.233,48.115 ; v3(83.66,43.253) 83.704,43.253 84.016,43.565 U2.R8@84.06,43.565 ; U2.B8@84.059,35.094 v3@84.384,35.419 ; U2.D8@84.059,36.394 84.419,36.034 v3@84.419,35.503 ; U2.F8@84.059,37.719 84.072,37.707 85.122,37.707 85.134,37.719 85.147,37.707 86.447,37.707 U2.F5@86.459,37.694 ; U2.H8@84.059,39.015 84.081,39.015 84.131,38.965 v3(84.809,38.965) ; U2.U8@84.059,44.844 84.074,44.829 84.426,44.829 84.46,44.794 v3@84.509,44.794 ; U2.W8@84.06,46.167 v3@84.38,46.487 ; v3(86.01,43.565) 86.042,43.532 U2.R5@86.422,43.532 ; v3(86.085,46.49) 86.11,46.49 86.435,46.165 U2.W5@86.46,46.165 ; v3(86.145,39.34) U2.H5@86.46,39.025 ; U2.B5@86.459,35.094 86.059,35.494 86.089,35.524 86.089,36.044 U2.D5@86.46,36.415 ; v3@87.679,45.243 88.032,44.891 88.032,44.883 U2.U3@88.059,44.856 ; v3(87.685,37.39) 87.733,37.39 87.817,37.474 88.037,37.694 U2.F3@88.059,37.694 ; v3(87.685,40.665) 87.697,40.665 88.046,40.316 U2.K3@88.059,40.316 ; U2.T2@88.832,44.199 88.854,44.199 89.134,43.919 89.284,43.919 89.95,43.253 90.025,43.253 v3@90.059,43.219 ; U2.G2@88.859,38.344 88.881,38.344 v3@89.171,38.635 ; v3(89.285,38.665) 89.298,38.665 89.628,38.995 89.658,38.995 89.659,38.994 v3@90.109,38.994 ; U2.D1@89.659,36.394 89.984,36.719 C15.1@91.159,36.719 ; U2.K1@89.659,40.307 89.659,40.294 v3@90.109,40.294 ; U2.N1@89.659,42.244 89.95,42.535 90.025,42.535 v3@90.059,42.569 ; v3(80.415,40.235) 80.78,40.235 U2.K12@80.842,40.297
  Top Layer w0.3: v3@90.059,42.569 v3@90.059,43.219 ; 90.259,43.014 91.079,43.014 C14.1@91.184,43.119
  Bottom Layer w0.15: C83.2@65.35,43.425 v2@65.627,43.148 ; C82.2@65.352,41.603 65.452,41.703 65.452,41.862 v2@65.625,42.035 ; v2@65.625,42.075 65.625,42.143 65.675,42.193 v2@65.675,42.99 ; v2@65.673,42.027 66.023,42.027 66.183,41.867 C75.2@66.218,41.867 ; C75.2@66.205,41.9 66.305,41.8 66.331,41.8 66.431,41.7 66.452,41.7 66.555,41.597 66.555,41.109 66.474,41.028 66.474,40.824 66.47,40.82
  Bottom Layer w0.16: C75.2@66.175,41.9 66.27,41.995 66.27,42.018 66.404,42.152 66.404,42.354 v2(66.45,42.4) ; C77.1@66.25,40.6 66.345,40.695 66.348,40.695 66.47,40.817 66.47,40.82
  Bottom Layer w0.2: v2(65.75,39) 65.476,38.726 65.466,38.726 65.463,38.723 65.349,38.723 C76.2@65.274,38.648 65.349,38.573 65.607,38.573 65.92,38.26 v2(65.97,38.26)
  Bottom Layer w0.22: v3@84.509,44.79 84.73,44.569 85.105,44.569 C21.1@85.109,44.565 ; R2.2@85.409,35.215 85.459,35.215 85.549,35.305 85.549,35.355 85.684,35.49 v3(86.06,35.49)
  Bottom Layer w0.3: C12.1@80.411,47.18 80.41,46.671 80.547,46.534 v3@80.547,46.485 ; v3@82.061,46.535 82.08,46.554 82.08,47.029 v3@82.836,47.785 ; C19.1@82.26,34.705 82.3,34.744 83.653,34.744 84.324,35.415 84.378,35.415 84.402,35.44 84.577,35.265 R2.2@85.461,35.265 ; v3(82.835,47.79) 82.834,48.365 C16.1@82.91,48.441 ; C16.1@82.911,48.39 82.996,48.475 82.996,49.225 C10.2@83.186,49.415 ; v3@84.381,46.485 86.086,46.485 86.086,46.534 85.991,46.629 85.991,47.499 86.04,47.499 86.13,47.59 C17.1@87.036,47.59 87.17,47.725 87.626,47.725 v3@87.66,47.76 ; v3(86.06,35.49) 87.077,34.473 87.077,33.915 87.104,33.915 87.489,33.531 87.998,33.531 88.017,33.511 88.088,33.455 88.162,33.397 88.553,33.397 88.58,33.345 C18.1@88.705,33.244 ; C18.1@88.604,33.345 C18.1@88.705,33.244 ; C18.1@88.71,33.24 C18.1@88.705,33.244 ; C11.2@89.834,32.94 89.009,32.94 C18.1@88.705,33.244 ; v3@90.109,40.29 90.143,40.324 90.718,40.324 C20.1@90.759,40.365
  other v1: 34.925,25.05 36.625,25.05 34.9,27.175 36.625,27.2
  other v2: 65.743,43
  other v3: 84.375,35.44 80.46,36.045 89.985,36.715 82.085,37.315 85.21,37.765 90.11,38.99 82.06,39.94 90.11,40.29 82.86,42.05 90.06,42.565 90.06,43.215 84.479,44.694 82.06,46.54
VDD3V3_USB: C61.1 C251.2 U1.AE21 U1.AE22 U26.38 | length 53.1
  Top Layer w0.09: U1.AE21@66.375,35.825 U1.AE22@66.875,35.825 ; U1.AE22@66.902,35.798 67.125,35.575 67.125,35.221 67.295,35.052 67.295,33.593 v2(67.3,33.588)
  Top Layer w0.1: U1.AE22@66.875,35.825 U1.AE22@66.902,35.798
  Top Layer w0.25: U26.38@26.488,38.694 26.488,37.844 28.138,36.194 28.138,35.764 28.288,35.614 29.693,35.614 30.013,35.294
  Top Layer w0.3: 30.013,35.294 31.088,34.219 v1(31.088,29.645)
  Signal Layer 2 w0.3: v1(31.088,29.645) 60.831,29.645 64.774,33.588 v2(67.3,33.588)
  Bottom Layer w0.3: v2(67.3,33.588) C251.2@67.89,33.588
VDD_EMMC: C9.2 C117.2 C190.1 U26.32 U37.E6 U37.F5 U37.J10 U37.K9 | length 98.9
  Top Layer w0.2: U37.E6@76.425,57.655 76.73,57.655 76.88,57.805 v1(76.975,57.805) 76.975,57.213 76.925,57.163 U37.F5@76.925,57.155 ; v1(78.35,59.055) v1@78.425,59.13 ; U37.J10@78.425,59.655 78.425,59.225 78.417,59.217 78.417,59.138 v1@78.425,59.13 ; U37.K9@78.925,59.155 78.545,59.155 78.512,59.122 78.433,59.122 v1@78.425,59.13
  Top Layer w0.3: 24.088,38.169 U26.32@24.088,38.694
  Top Layer w0.4: v1@18.352,36.719 C190.1@19.038,36.719 ; C190.1@19.043,36.867 19.511,37.335 23.41,37.335 24.063,37.989 24.063,38.094
  Top Layer w0.5: v1(18.336,36.735) v1@18.343,36.742
  Top Layer w0.7: v1@18.343,36.742 18.343,62.193 v1(18.35,62.2)
  Signal Layer 2 w0.5: v1(76.975,57.805) 76.975,57.819 77.05,57.894 77.05,58.059 77.431,58.44 77.819,58.44 78.2,58.821 78.2,58.891 78.34,59.032 v1@78.34,59.045
  Signal Layer 2 w0.7: v1(18.35,62.2) 72.58,62.2 76.175,58.605 76.225,58.605 76.65,58.18 76.65,58.13 v1@76.886,57.894
  Bottom Layer w0.2: C9.2@76.615,58.58 76.615,58.074 76.884,57.805 v1(76.975,57.805) ; v1(78.35,59.055) 78.35,59.739 C117.2@78.475,59.864
VDD_free: C215.2 U26.36 | length 3.1
  Top Layer w0.25: U26.36@25.688,38.419 25.688,37.019 v1(26.013,36.694) 26.013,36.672 25.738,36.397 C215.2@25.738,35.519
VDDA1V8_AON: C189.1 C234.2 U1.AB3 U1.W2 U26.1 | length 39.5
  Top Layer w0.09: 56.026,38.692 56.705,38.692 56.837,38.825 U1.W2@56.875,38.825 ; v2@57.825,37.775 v2(57.825,37.8)
  Top Layer w0.1: v2(54.932,38.744) 54.99,38.801 55.205,38.801 55.267,38.863 55.805,38.863 55.975,38.692 56.026,38.692
  Top Layer w0.15: U1.AB3@57.375,37.325 v2@57.825,37.775
  Top Layer w0.2: U26.1@27.963,39.344 27.985,39.344 27.985,38.247 28.163,38.069 28.163,37.669 28.438,37.394 ; 28.446,37.394 28.446,36.916 28.533,36.829 28.533,36.749 29.263,36.019 29.888,36.019 30.188,35.719 v2(30.431,35.719)
  Signal Layer 2 w0.3: v2(30.431,35.719) 41.409,35.719 41.778,35.35 52.552,35.35 53.025,35.823 v2(53.025,35.875)
  Bottom Layer w0.3: v2(53.025,35.875) 53.052,35.875 53.152,35.775 53.829,35.775 53.836,35.769 54.451,35.769 54.627,35.944 54.627,36.412 54.891,36.675 55.461,36.675 55.662,36.877 56.088,36.877 57.012,37.8 ; v2(54.932,38.744) 54.936,38.748 C234.2@56.064,38.748 56.199,38.613 56.338,38.613 56.479,38.472 56.479,38.333 57.012,37.8 ; v2(57.825,37.8) 57.012,37.8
